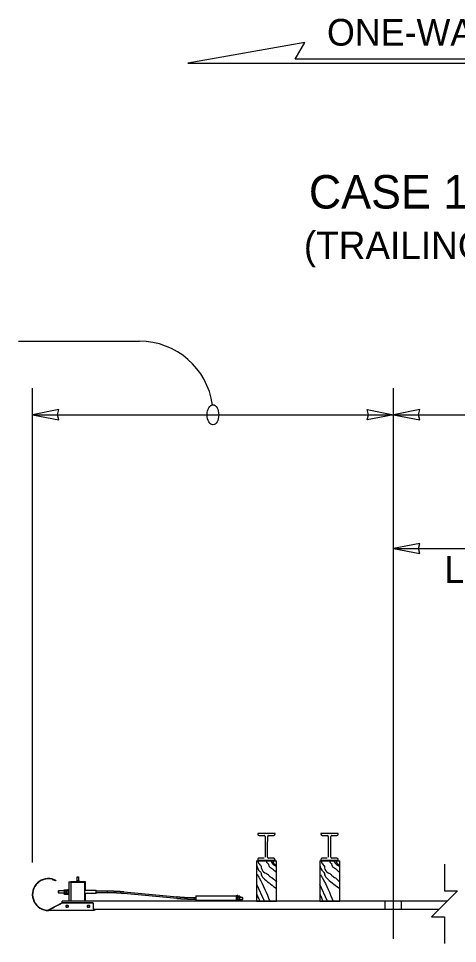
# Model space of a CAD drawing. Extents: x 99862 to 103680, y 99470 to 102076.
# Drawn here: x 100709 to 100972, y 100317 to 100870 of the extents above; entities that cross this region are included whole.
import ezdxf

# ---------------------------------------------------------------- set-up
doc = ezdxf.new("R2010")
doc.units = 0
for name, color, linetype in [('Level 1', 7, 'Continuous'), ('Level 10', 7, 'Continuous'), ('Level 13', 7, 'Continuous'), ('Level 15', 7, 'Continuous'), ('Level 2', 7, 'Continuous'), ('Level 20', 7, 'Continuous'), ('Level 3', 7, 'Continuous'), ('Level 4', 7, 'Continuous'), ('Level 5', 7, 'Continuous'), ('Level 6', 7, 'Continuous'), ('Level 7', 7, 'Continuous'), ('Level 9', 7, 'Continuous')]:
    doc.layers.add(name, color=color, linetype=linetype)

msp = doc.modelspace()

# ---------------------------------------------------------------- linework, layer by layer
at = {"layer": 'Level 1'}
for p, q in [((100928.27, 100342.54), (100928.27, 100337.5)), ((100938.05, 100342.64), (100938.05, 100337.66))]:
    msp.add_line(p, q, dxfattribs=at)
at = {"layer": 'Level 10'}
for p, q in [((100851.64, 100366.5), (100863.64, 100366.5)), ((100851.64, 100366.5), (100851.64, 100342.5)), ((100863.64, 100342.5), (100863.64, 100366.5)), ((100889.41, 100366.5), (100901.41, 100366.5)), ((100889.41, 100366.5), (100889.41, 100342.5)), ((100901.41, 100342.5), (100901.41, 100366.5)), ((100851.64, 100342.5), (100863.64, 100342.5)), ((100856.7, 100342.42), (100856.7, 100342.5)), ((100856.7, 100342.42), (100856.7, 100342.5)), ((100858.57, 100342.5), (100858.57, 100342.42)), ((100858.57, 100342.5), (100858.57, 100342.42)), ((100889.41, 100342.5), (100901.41, 100342.5)), ((100894.47, 100342.42), (100894.47, 100342.5)), ((100894.47, 100342.42), (100894.47, 100342.5)), ((100896.34, 100342.5), (100896.34, 100342.42)), ((100896.34, 100342.5), (100896.34, 100342.42))]:
    msp.add_line(p, q, dxfattribs=at)
at = {"layer": 'Level 13'}
for p, q in [((100851.51, 100352.59), (100856.11, 100342.58)), ((100889.28, 100352.59), (100893.88, 100342.58))]:
    msp.add_line(p, q, dxfattribs=at)
for points in [[(100852.4, 100366.49), (100853.67, 100364.21), (100854.12, 100363.81), (100854.48, 100362.42), (100856.6, 100359.4), (100858.51, 100358.31), (100858.92, 100357.76), (100861.05, 100356.31), (100861.23, 100356.17), (100863.65, 100353.89)], [(100857.37, 100366.49), (100858.18, 100365.14), (100858.58, 100364.97), (100858.75, 100364.26), (100859.99, 100362.49), (100861.23, 100361.83), (100861.56, 100361.39), (100863.61, 100359.99)], [(100860.06, 100366.51), (100860.48, 100365.82), (100861.38, 100364.53), (100862.37, 100363.93), (100863.54, 100363.2)], [(100861.47, 100366.47), (100861.83, 100365.15), (100863.54, 100364.03)], [(100890.16, 100366.49), (100891.44, 100364.21), (100891.89, 100363.81), (100892.24, 100362.42), (100894.37, 100359.4), (100896.28, 100358.31), (100896.69, 100357.76), (100898.82, 100356.31), (100899, 100356.17), (100901.42, 100353.89)], [(100895.13, 100366.49), (100895.95, 100365.14), (100896.35, 100364.97), (100896.52, 100364.26), (100897.76, 100362.49), (100899, 100361.83), (100899.32, 100361.39), (100901.38, 100359.99)], [(100897.83, 100366.51), (100898.24, 100365.82), (100899.15, 100364.53), (100900.14, 100363.93), (100901.31, 100363.2)], [(100899.24, 100366.47), (100899.6, 100365.15), (100901.31, 100364.03)], [(100851.58, 100364.23), (100853.68, 100360.09), (100854.13, 100359.68), (100854.48, 100358.29), (100856.43, 100355.58), (100863.64, 100349.99)], [(100889.35, 100364.23), (100891.45, 100360.09), (100891.9, 100359.68), (100892.25, 100358.29), (100894.2, 100355.58), (100901.41, 100349.99)], [(100852.04, 100358.37), (100853.19, 100356.36), (100859.6, 100342.44)], [(100889.81, 100358.37), (100890.96, 100356.36), (100897.37, 100342.44)], [(100851.62, 100346.66), (100851.77, 100346.4), (100851.92, 100346.14), (100852.19, 100345.6), (100852.68, 100344.49), (100853.13, 100343.36), (100853.36, 100342.8), (100853.6, 100342.24)], [(100889.39, 100346.66), (100889.54, 100346.4), (100889.68, 100346.14), (100889.96, 100345.6), (100890.44, 100344.49), (100890.9, 100343.36), (100891.13, 100342.8), (100891.37, 100342.24)]]:
    msp.add_spline(points, degree=3, dxfattribs=at)
at = {"layer": 'Level 15'}
msp.add_line((100933.41, 100319.89), (100933.41, 100649.28), dxfattribs=at)
msp.add_lwpolyline([(100963.91, 100364.62), (100963.91, 100348.62), (100971.65, 100348.62), (100956.16, 100333.13), (100963.91, 100333.13), (100963.91, 100317.13)], dxfattribs=at)
msp.add_ellipse((100825.59, 100633.28), major_axis=(0, -6), ratio=0.57735, dxfattribs=at)
at = {"layer": 'Level 2'}
for p, q in [((100735.54, 100342.47), (100735.54, 100342.5)), ((100965.53, 100342.5), (100735.54, 100342.5)), ((100735.54, 100341.42), (100735.54, 100342.47)), ((100960.44, 100337.4), (100754.27, 100337.4))]:
    msp.add_line(p, q, dxfattribs=at)
at = {"layer": 'Level 20'}
for p, q in [((100709.47, 100677.28), (100781.68, 100677.28)), ((100717.77, 100365.56), (100717.77, 100649.3)), ((100717.77, 100633.28), (100933.41, 100633.28)), ((100933.41, 100633.28), (101491.3, 100633.28)), ((100933.41, 100553.33), (101355.28, 100553.33))]:
    msp.add_line(p, q, dxfattribs=at)
for points in [[(100717.77, 100633.28), (100733.5, 100630.2), (100732.77, 100633.28), (100733.5, 100636.36)], [(100933.41, 100633.28), (100917.68, 100630.2), (100918.41, 100633.28), (100917.68, 100636.36)], [(100933.41, 100633.28), (100949.13, 100630.2), (100948.4, 100633.28), (100949.13, 100636.36)], [(100933.41, 100553.33), (100949.13, 100550.25), (100948.4, 100553.33), (100949.13, 100556.41)]]:
    msp.add_lwpolyline(points, close=True, dxfattribs=at)
msp.add_arc((100781.68, 100633.28), 44, 7.8051, 90, dxfattribs=at)
at = {"layer": 'Level 3'}
for p, q in [((100729.52, 100355.71), (100729.48, 100355.53)), ((100731.68, 100354.9), (100731.6, 100354.74)), ((100744.44, 100356.86), (100744.57, 100357)), ((100744.44, 100356.86), (100745.38, 100356.86)), ((100744.44, 100354.69), (100744.44, 100356.86)), ((100744.57, 100357), (100745.25, 100357)), ((100745.25, 100357), (100745.38, 100356.86)), ((100745.38, 100356.86), (100745.38, 100354.69)), ((100735.52, 100341.42), (100727.27, 100337.05)), ((100753.89, 100341.42), (100735.52, 100341.42)), ((100753.89, 100341.31), (100735.57, 100341.3)), ((100738.68, 100339.9), (100738.35, 100339.9)), ((100738.68, 100338.8), (100738.35, 100338.8)), ((100751.43, 100339.9), (100751.1, 100339.9)), ((100751.43, 100338.8), (100751.1, 100338.8)), ((100754.27, 100341.01), (100754.27, 100341.12)), ((100754.27, 100337.58), (100754.27, 100341.01)), ((100754.27, 100337.58), (100754.27, 100336.86)), ((100754.27, 100336.86), (100735.52, 100336.86))]:
    msp.add_line(p, q, dxfattribs=at)
msp.add_lwpolyline([(101095.52, 100846.02), (100874.78, 100846.02), (100880.48, 100855.87), (100810.51, 100843.54), (101095.52, 100843.54)], close=True, dxfattribs=at)
for radius, end in [(9.56, 270.2805), (9.37, 270)]:
    msp.add_arc((100727.27, 100346.42), radius, 76.3846, end, dxfattribs=at)
for centre, major_axis, start_param, end_param in [((100738.35, 100339.35), (0.68, 0), 1.570796, 4.712389), ((100738.68, 100339.35), (0.68, 0), 4.712389, 7.853982), ((100751.1, 100339.35), (0.68, 0), 1.570796, 4.712389), ((100751.43, 100339.35), (0.68, 0), 4.712389, 7.853982), ((100753.89, 100341.12), (-0.375, 0), 3.141593, 4.712389), ((100753.89, 100341.01), (-0.375, 0), 3.141593, 4.712389)]:
    msp.add_ellipse(centre, major_axis=major_axis, ratio=0.807578, start_param=start_param, end_param=end_param, dxfattribs=at)
for points, degree in [([(100729.48, 100355.53), (100729.56, 100355.51), (100729.73, 100355.47), (100729.97, 100355.4), (100730.2, 100355.32), (100730.42, 100355.25), (100730.63, 100355.17), (100730.82, 100355.1), (100731.08, 100354.99), (100731.35, 100354.86), (100731.56, 100354.75), (100731.59, 100354.74), (100731.6, 100354.74)], 3), ([(100729.52, 100355.71), (100730.75, 100355.42), (100731.68, 100354.9), (100731.68, 100354.9)], 2), ([(100735.57, 100341.3), (100732.84, 100339.82), (100730.1, 100338.34), (100727.36, 100336.88), (100727.34, 100336.87), (100727.33, 100336.87), (100727.32, 100336.86)], 3), ([(100754.64, 100337.15), (100754.61, 100337.13), (100754.55, 100337.1), (100754.47, 100337.07), (100754.37, 100337.05), (100754.31, 100337.05), (100754.27, 100337.05)], 3), ([(100754.74, 100336.98), (100754.59, 100336.9), (100754.46, 100336.86), (100754.27, 100336.86)], 2), ([(100755.09, 100337.4), (100754.8, 100337.24), (100754.64, 100337.15)], 2), ([(100755.46, 100337.4), (100755.32, 100337.32), (100755.19, 100337.24), (100754.9, 100337.08), (100754.74, 100336.98)], 3), ([(100735.52, 100336.86), (100732.77, 100336.86), (100730.02, 100336.86), (100727.27, 100336.86)], 2), ([(100727.32, 100336.86), (100727.32, 100336.86), (100727.32, 100336.86), (100727.32, 100336.86)], 2), ([(100754.27, 100336.86), (100754.27, 100336.86), (100754.27, 100336.86), (100754.27, 100336.86)], 2)]:
    msp.add_open_spline(points, degree=degree, dxfattribs=at)
at = {"layer": 'Level 4'}
for p, q in [((100744.1, 100354), (100740.79, 100354)), ((100742.66, 100353.72), (100740.79, 100353.72)), ((100749.04, 100353.62), (100740.79, 100353.62)), ((100740.79, 100353.62), (100740.79, 100342.5)), ((100749.41, 100354), (100745.72, 100354)), ((100749.13, 100353.72), (100747.16, 100353.72)), ((100749.04, 100342.5), (100749.04, 100353.62)), ((100749.13, 100348.93), (100749.13, 100353.72)), ((100749.41, 100348.93), (100749.41, 100354)), ((100749.13, 100342.5), (100749.13, 100347.06)), ((100749.41, 100342.5), (100749.41, 100347.06))]:
    msp.add_line(p, q, dxfattribs=at)
at = {"layer": 'Level 5'}
for p, q in [((100747.16, 100353.87), (100742.66, 100353.87)), ((100742.66, 100353.87), (100742.66, 100353.62)), ((100747.16, 100353.87), (100747.16, 100353.62))]:
    msp.add_line(p, q, dxfattribs=at)
at = {"layer": 'Level 6'}
for p, q in [((100733.41, 100348.61), (100733.54, 100348.75)), ((100733.41, 100347.38), (100733.41, 100348.61)), ((100733.41, 100348.61), (100733.41, 100348.61)), ((100733.54, 100347.25), (100733.54, 100348.75)), ((100733.54, 100348.75), (100736.69, 100348.75)), ((100749.04, 100348.93), (100755.82, 100348.93)), ((100755.82, 100347.06), (100755.82, 100348.93)), ((100755.82, 100348.93), (100755.82, 100348.93)), ((100755.82, 100348.56), (100762.37, 100348.56)), ((100762.37, 100348.56), (100762.37, 100347.43)), ((100772.4, 100348.12), (100804.27, 100345.07)), ((100733.54, 100347.25), (100733.41, 100347.38)), ((100736.69, 100347.25), (100733.54, 100347.25)), ((100755.82, 100347.06), (100749.04, 100347.06)), ((100762.37, 100347.43), (100755.82, 100347.43)), ((100804.16, 100343.95), (100772.3, 100347)), ((100814.2, 100344.64), (100814.2, 100343.51)), ((100814.2, 100344.64), (100815.41, 100344.64)), ((100815.41, 100343.51), (100814.2, 100343.51)), ((100815.41, 100345.61), (100839.41, 100345.61)), ((100815.41, 100345.61), (100815.41, 100342.98)), ((100815.41, 100342.98), (100839.41, 100342.98)), ((100815.41, 100342.98), (100815.41, 100342.5)), ((100839.41, 100345.76), (100840.16, 100345.76)), ((100839.41, 100345.76), (100839.41, 100342.5)), ((100840.16, 100345.76), (100840.16, 100342.5)), ((100841.72, 100344.83), (100843.02, 100344.83)), ((100843.02, 100343.33), (100841.72, 100343.33)), ((100843.02, 100344.83), (100843.02, 100343.33)), ((100843.02, 100344.83), (100843.16, 100344.69)), ((100843.16, 100343.46), (100843.02, 100343.33)), ((100843.16, 100344.69), (100843.16, 100343.46)), ((100843.16, 100343.46), (100843.16, 100343.46))]:
    msp.add_line(p, q, dxfattribs=at)
for centre, start_param in [((100772.35, 100347.56), 3.141597), ((100804.22, 100344.51), 3.141588)]:
    msp.add_ellipse(centre, major_axis=(-0.054, -0.56), ratio=0.548823, start_param=start_param, end_param=6.283185, dxfattribs=at)
for points in [[(100762.37, 100348.56), (100765.91, 100348.56), (100769.45, 100348.41), (100772.4, 100348.12)], [(100772.3, 100347), (100769.38, 100347.28), (100765.88, 100347.43), (100762.37, 100347.43)], [(100814.2, 100343.51), (100810.66, 100343.51), (100807.12, 100343.67), (100804.16, 100343.95)], [(100804.27, 100345.07), (100807.19, 100344.79), (100810.69, 100344.64), (100814.2, 100344.64)]]:
    msp.add_open_spline(points, degree=2, dxfattribs=at)
at = {"layer": 'Level 7'}
for p, q in [((100739.57, 100354), (100739.57, 100342.5)), ((100739.57, 100354), (100740.79, 100354)), ((100740.79, 100354), (100740.79, 100353.62))]:
    msp.add_line(p, q, dxfattribs=at)
at = {"layer": 'Level 9'}
for p, q in [((100856.74, 100381.07), (100856.73, 100374.93)), ((100858.27, 100374.93), (100858.28, 100381.07)), ((100894.51, 100381.07), (100894.5, 100374.93)), ((100896.04, 100374.93), (100896.05, 100381.07)), ((100856.73, 100374.93), (100856.72, 100368.79)), ((100858.27, 100368.79), (100858.27, 100374.93)), ((100894.5, 100374.93), (100894.49, 100368.79)), ((100896.04, 100368.79), (100896.04, 100374.93)), ((100744.1, 100354.63), (100744.21, 100354.69)), ((100744.1, 100354.63), (100744.1, 100353.87)), ((100744.91, 100354.69), (100744.21, 100354.69)), ((100744.51, 100354.63), (100744.51, 100353.87)), ((100745.51, 100354.69), (100744.91, 100354.69)), ((100745.32, 100354.63), (100745.32, 100353.87)), ((100745.38, 100355.21), (100745.38, 100355.21)), ((100745.38, 100355.21), (100745.38, 100355.21)), ((100745.51, 100354.69), (100745.53, 100354.69)), ((100745.61, 100354.69), (100745.53, 100354.69)), ((100745.61, 100354.69), (100745.72, 100354.63)), ((100745.72, 100354.63), (100745.72, 100353.87)), ((100736.69, 100349.12), (100736.79, 100349.3)), ((100736.69, 100349.12), (100736.69, 100348.98)), ((100736.69, 100348.96), (100736.69, 100348.98)), ((100736.69, 100348.96), (100736.69, 100348)), ((100736.69, 100348), (100736.69, 100346.87)), ((100736.79, 100349.3), (100738, 100349.3)), ((100736.79, 100348.65), (100738, 100348.65)), ((100738, 100349.12), (100738.11, 100349.3)), ((100738, 100348.65), (100738, 100349.3)), ((100738, 100348.96), (100738, 100348.98)), ((100738, 100347.35), (100738, 100348.65)), ((100738, 100348), (100738, 100347.99)), ((100738, 100348), (100738, 100348)), ((100738.11, 100349.3), (100739.32, 100349.3)), ((100738.11, 100348.65), (100739.32, 100348.65)), ((100739.32, 100349.66), (100739.57, 100349.66)), ((100739.32, 100346.33), (100739.32, 100349.66)), ((100739.32, 100349.3), (100739.32, 100349.66)), ((100739.32, 100348.65), (100739.32, 100349.3)), ((100739.32, 100347.35), (100739.32, 100348.65)), ((100749.04, 100352.96), (100749.13, 100352.96)), ((100749.13, 100352.03), (100749.04, 100352.03)), ((100736.79, 100346.7), (100736.69, 100346.87)), ((100736.79, 100347.35), (100738, 100347.35)), ((100736.79, 100346.7), (100738, 100346.7)), ((100738, 100346.7), (100738, 100347.35)), ((100738.11, 100346.7), (100738, 100346.87)), ((100738.11, 100347.35), (100739.32, 100347.35)), ((100738.11, 100346.7), (100739.32, 100346.7)), ((100739.32, 100346.7), (100739.32, 100347.35)), ((100739.32, 100346.33), (100739.57, 100346.33)), ((100840.41, 100345.74), (100840.16, 100345.74)), ((100840.41, 100345.74), (100840.41, 100342.5)), ((100841.62, 100345.37), (100840.41, 100345.37)), ((100840.41, 100345.37), (100840.41, 100344.72)), ((100841.62, 100344.72), (100840.41, 100344.72)), ((100840.41, 100344.72), (100840.41, 100343.43)), ((100840.41, 100343.43), (100840.41, 100342.78)), ((100841.62, 100343.43), (100840.41, 100343.43)), ((100840.41, 100342.78), (100840.41, 100342.5)), ((100841.62, 100342.78), (100840.41, 100342.78)), ((100841.62, 100345.37), (100841.72, 100345.2)), ((100841.72, 100342.95), (100841.62, 100342.78)), ((100841.72, 100344.08), (100841.72, 100345.2)), ((100841.72, 100343.11), (100841.72, 100344.08)), ((100841.72, 100343.11), (100841.72, 100343.09)), ((100841.72, 100342.95), (100841.72, 100343.09))]:
    msp.add_line(p, q, dxfattribs=at)
for points in [[(100857.51, 100382.93), (100852.34, 100382.94), (100852.34, 100382.45)], [(100853.13, 100381.66), (100856.15, 100381.66)], [(100862.68, 100382.44), (100862.68, 100382.92), (100857.51, 100382.93)], [(100858.87, 100381.66), (100861.89, 100381.65)], [(100895.28, 100382.93), (100890.11, 100382.94), (100890.11, 100382.45)], [(100890.9, 100381.66), (100893.92, 100381.66)], [(100900.45, 100382.44), (100900.45, 100382.92), (100895.28, 100382.93)], [(100896.64, 100381.66), (100899.66, 100381.65)], [(100852.32, 100367.42), (100852.32, 100366.94), (100857.49, 100366.93)], [(100856.13, 100368.2), (100853.11, 100368.21)], [(100857.49, 100366.93), (100862.66, 100366.92), (100862.66, 100367.41)], [(100861.88, 100368.2), (100858.86, 100368.2)], [(100890.09, 100367.42), (100890.09, 100366.94), (100895.26, 100366.93)], [(100893.9, 100368.2), (100890.88, 100368.21)], [(100895.26, 100366.93), (100900.43, 100366.92), (100900.43, 100367.41)], [(100899.64, 100368.2), (100896.63, 100368.2)]]:
    msp.add_lwpolyline(points, dxfattribs=at)
for centre, radius, start, end in [((100853.13, 100382.45), 0.788, 179.9273, 269.9273), ((100856.15, 100381.07), 0.591, 359.9273, 89.9273), ((100858.87, 100381.07), 0.591, 89.9273, 179.9273), ((100861.89, 100382.44), 0.788, 269.9273, 359.9273), ((100890.9, 100382.45), 0.788, 179.9273, 269.9273), ((100893.92, 100381.07), 0.591, 359.9273, 89.9273), ((100896.64, 100381.07), 0.591, 89.9273, 179.9273), ((100899.66, 100382.44), 0.788, 269.9273, 359.9273), ((100853.11, 100367.42), 0.788, 89.9273, 179.9478), ((100858.86, 100368.79), 0.591, 179.9273, 269.9273), ((100861.87, 100367.41), 0.788, 359.9478, 89.9273), ((100890.88, 100367.42), 0.788, 89.9273, 179.9478), ((100896.63, 100368.79), 0.591, 179.9273, 269.9273), ((100899.64, 100367.41), 0.788, 359.9478, 89.9273)]:
    msp.add_arc(centre, radius, start, end, dxfattribs=at)
for points, degree in [([(100744.1, 100354.63), (100744.17, 100354.66), (100744.23, 100354.69), (100744.37, 100354.69), (100744.44, 100354.66), (100744.51, 100354.63)], 3), ([(100744.1, 100354.63), (100744.1, 100354.63), (100744.1, 100354.63), (100744.1, 100354.63)], 2), ([(100744.91, 100354.69), (100744.77, 100354.69), (100744.64, 100354.66), (100744.51, 100354.63)], 2), ([(100745.32, 100354.63), (100745.18, 100354.66), (100745.05, 100354.69), (100744.91, 100354.69)], 2), ([(100745.32, 100354.63), (100745.38, 100354.66), (100745.45, 100354.69), (100745.51, 100354.69)], 2), ([(100745.53, 100354.69), (100745.59, 100354.69), (100745.66, 100354.66), (100745.72, 100354.63)], 2), ([(100745.72, 100354.63), (100745.72, 100354.63), (100745.72, 100354.63), (100745.72, 100354.63)], 2), ([(100736.69, 100348.98), (100736.7, 100349.09), (100736.73, 100349.19), (100736.79, 100349.3)], 2), ([(100736.79, 100348.65), (100736.73, 100348.75), (100736.7, 100348.85), (100736.69, 100348.96)], 2), ([(100736.79, 100348.65), (100736.73, 100348.43), (100736.69, 100348.22), (100736.69, 100348)], 2), ([(100736.69, 100348), (100736.69, 100347.78), (100736.73, 100347.56), (100736.79, 100347.35)], 2), ([(100738, 100348.98), (100738.01, 100349.09), (100738.05, 100349.19), (100738.11, 100349.3)], 2), ([(100738.11, 100348.65), (100738.05, 100348.75), (100738.01, 100348.85), (100738, 100348.96)], 2), ([(100738.11, 100348.65), (100738.04, 100348.43), (100738, 100348.22), (100738, 100348)], 2), ([(100738, 100348), (100738, 100347.78), (100738.04, 100347.56), (100738.11, 100347.35)], 2), ([(100736.79, 100346.7), (100736.73, 100346.8), (100736.69, 100346.91), (100736.69, 100347.13), (100736.73, 100347.24), (100736.79, 100347.35)], 3), ([(100736.79, 100346.7), (100736.79, 100346.7), (100736.79, 100346.7), (100736.79, 100346.7)], 2), ([(100738.11, 100346.7), (100738.04, 100346.8), (100738.01, 100346.91), (100738, 100347.13), (100738.04, 100347.24), (100738.11, 100347.35)], 3), ([(100738.11, 100346.7), (100738.11, 100346.7), (100738.11, 100346.7), (100738.11, 100346.7)], 2), ([(100841.62, 100345.37), (100841.62, 100345.37), (100841.62, 100345.37), (100841.62, 100345.37)], 2), ([(100841.62, 100345.37), (100841.68, 100345.27), (100841.72, 100345.16), (100841.72, 100344.94), (100841.68, 100344.83), (100841.62, 100344.72)], 3), ([(100841.72, 100344.08), (100841.72, 100344.29), (100841.68, 100344.51), (100841.62, 100344.72)], 2), ([(100841.62, 100343.43), (100841.68, 100343.64), (100841.72, 100343.86), (100841.72, 100344.08)], 2), ([(100841.62, 100343.43), (100841.68, 100343.32), (100841.72, 100343.22), (100841.72, 100343.11)], 2), ([(100841.72, 100343.09), (100841.72, 100342.98), (100841.68, 100342.88), (100841.62, 100342.78)], 2), ([(100841.62, 100342.78), (100841.62, 100342.78), (100841.62, 100342.78), (100841.62, 100342.78)], 2)]:
    msp.add_open_spline(points, degree=degree, dxfattribs=at)

# ---------------------------------------------------------------- texts
at = {"layer": 'Level 20'}
for s, height, p in [('ONE-WAY TRAFFIC', 16, (100893.71, 100854.02)), ('CASE 10B-31', 20, (100882.89, 100756.62)), ('LENGTH VARIES (GREATER THAN ', 16, (100963.84, 100532.79))]:
    msp.add_text(s, height=height, dxfattribs=at).set_placement(p)
msp.add_text('(TRAILING END)', height=16.5, rotation=0, dxfattribs=at).set_placement((100879.9, 100726.37))

doc.saveas('drawing.dxf')
